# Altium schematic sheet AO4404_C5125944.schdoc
size 127 x 101 mm
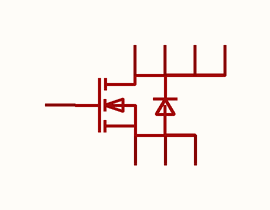
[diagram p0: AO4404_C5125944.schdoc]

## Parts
Q?  ao4404  [SOP-8_L4.9-W3.9-P1.27-LS6.0-BL]  (value not drawn)

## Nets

Not connected (* = marked no-connect by the designer): Q? 1(S) 2(S) 3(S) 4(G) 5(D) 6(D) 7(D) 8(D)

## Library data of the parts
Q? = ao4404: 数量:1个N沟道;漏源电压(Vdss):20V;连续漏极电流(Id):12A;导通电阻(RDS(on)):20mΩ@10V;耗散功率(Pd):4.1W;阈值电压(Vgs(th)):3V;; Manufacturer: UMW(友台半导体); Symbol: AO4404_C5125944; AddInBom: yes; ModelId: 75c24a7891ee4dd6bdac16a7163ff87e; ModelName: SOP-8_L4.9-W3.9-P1.27-LS6.0-BL-1; ModelTransform: 192.913,236.22,0,0,0,0,-0.393,2.749,0; Number: 1个N沟道; Drain to Source Voltage: 20V; Current - Continuous Drain(Id): 12A; Pd - Power Dissipation: 4.1W; Gate Threshold Voltage (Vgs(th)): 3V; Gate Charge(Qg): 15nC@10V; Input Capacitance(Ciss): 800pF; Reverse Transfer Capacitance (Crss@Vds): 73pF; Output Capacitance(Coss): 165pF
